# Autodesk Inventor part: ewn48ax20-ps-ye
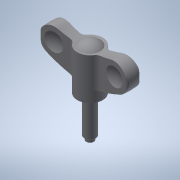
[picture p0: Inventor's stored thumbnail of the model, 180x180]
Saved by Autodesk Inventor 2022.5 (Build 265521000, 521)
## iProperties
Created: 2016-12
Part Number: ewn48ax20-ps-ye
Material: 一般
Document SubType Name: Modeling
Designer: imaocorp
Density: 1 g/cm^3
Appearance: 既定
Author: imaocorp
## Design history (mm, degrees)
node "ewn48ax20-ps-ye.x_t1"
node "ewn48ax20-ps-ye"
node "Base1"
